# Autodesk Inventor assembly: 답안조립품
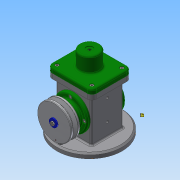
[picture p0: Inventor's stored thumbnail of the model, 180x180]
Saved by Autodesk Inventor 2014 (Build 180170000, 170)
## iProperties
Created: 2019-08
Part Number: 답안조립품
Document SubType Name: Assembly
Designer: NET
Author: NET
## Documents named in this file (18)
- C:\Users\NET\Desktop\490804V1020\답안조립품.iam
- C:\Users\NET\Desktop\490804V1020\본체.ipt
- C:\Users\NET\Desktop\490804V1020\E-링.ipt
- C:\Users\NET\Desktop\490804V1020\V-벨트풀리.ipt
- C:\Users\NET\Desktop\490804V1020\덮개.ipt
- C:\Users\NET\Desktop\490804V1020\뒤커버.ipt
- C:\Users\NET\Desktop\490804V1020\링크.ipt
- C:\Users\NET\Desktop\490804V1020\베어링 17 x 40 x 12.ipt
- C:\Users\NET\Desktop\490804V1020\볼트 M4 x 8.ipt
- C:\Users\NET\Desktop\490804V1020\볼트 M4 x 10.ipt
- C:\Users\NET\Desktop\490804V1020\슬라이더.ipt
- C:\Users\NET\Desktop\490804V1020\앞커버.ipt
- C:\Users\NET\Desktop\490804V1020\오일 실 17 30 8.ipt
- C:\Users\NET\Desktop\490804V1020\와셔 4x16.ipt
- C:\Users\NET\Desktop\490804V1020\클레비스 핀 6 x 22.ipt
- 클레비스 핀 6 x 22.ipt
- C:\Users\NET\Desktop\490804V1020\키 4 x 4 x 12.ipt
- C:\Users\NET\Desktop\490804V1020\편심축.ipt
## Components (2 placed, 2 different names)
1. E-링:1
2. V-벨트풀리:1
